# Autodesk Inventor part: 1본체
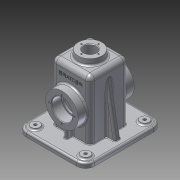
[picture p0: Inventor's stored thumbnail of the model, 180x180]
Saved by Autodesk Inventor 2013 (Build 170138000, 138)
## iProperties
Created: 2016-01
Part Number: 1본체
Material: 알루미늄 6061
Document SubType Name: Modeling
Designer: Administrator
Density: 2.71 g/cm^3
Mass: 805.142 g
Surface Area: 912.293 cm^2
Volume: 297.1 cm^3
Author: Administrator
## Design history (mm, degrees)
sketch "스케치1"
  geometry: L1 (-57.5, 65)-(57.5, 65); L2 (57.5, 65)-(57.5, -65); L3 (57.5, -65)-(-57.5, -65); L4 (-57.5, -65)-(-57.5, 65); L5 (-57.5, 65)-(57.5, -65); L6 (57.5, 65)-(-57.5, -65); 1 further point
  constraints: 12 end point, 2 midpoint, 2 parallel, 1 horizontal, 1 perpendicular
  dimensions: "d0" = 115 distance of L1.start L1.end; "d2" = 130 distance of L1.end L2.end
extrude "돌출1" new body sketch "스케치1" distance "d3" = 8; taper "d4" = 0 deg
fillet "모깎기1" dims "d5" = 15
sketch "스케치3"
  geometry: L1 (42.5, -60)-(-42.5, -60); L2 (-52.5, -50)-(-52.5, 50); L3 (-42.5, 60)-(42.5, 60); L4 (52.5, 50)-(52.5, -50); L5 (52.5, -60)-(-52.5, 60); L6 (-52.5, -60)-(52.5, 60); A1 r 10 centre (42.5, -50) between (42.5, -60) and (52.5, -50); A2 r 10 centre (42.5, 50) between (52.5, 50) and (42.5, 60); A3 r 10 centre (-42.5, 50) between (-42.5, 60) and (-52.5, 50); A4 r 10 centre (-42.5, -50) between (-52.5, -50) and (-42.5, -60); 1 further point
  constraints: 12 end point, 8 point on circle, 8 point on line, 8 tangent, 4 centre point, 3 equal radius, 2 midpoint, 2 parallel, 1 horizontal, 1 perpendicular
  dimensions: "d6" = 105 distance of L5.start L6.start; "d8" = 120 distance of L6.start L5.end; "d9" = 10 radius of A1
extrude "돌출2" join sketch "스케치3" distance "d10" = 2; taper "d11" = 0 deg
sketch "스케치7"
  geometry: L1 (-32.5, 32.5)-(32.5, 32.5); L2 (32.5, 32.5)-(32.5, -32.5); L3 (32.5, -32.5)-(-32.5, -32.5); L4 (-32.5, -32.5)-(-32.5, 32.5); L5 (-32.5, 32.5)-(32.5, -32.5); L6 (32.5, 32.5)-(-32.5, -32.5); 1 further point
  constraints: 12 end point, 2 midpoint, 2 parallel, 1 horizontal, 1 perpendicular
  dimensions: "d33" = 65 distance of L2.end L3.end; "d34" = 65 distance of L1.end L2.end
extrude "돌출4" join sketch "스케치7" distance "d35" = 100; taper "d36" = 0 deg
fillet "모깎기2" dims "d37" = 8
fillet "모깎기3" dims "d38" = 8
sketch "스케치8"
  geometry: C1 r 20 at (0, 0); 1 further point
  constraints: 1 centre point, 1 coincident
  dimensions: "d39" = 20 radius of C1
extrude "돌출5" join sketch "스케치8" distance "d40" = 10; taper "d41" = 0 deg
node "작업 평면1"
sketch "스케치10"
  geometry: L1 (-57.5, 0)-(-57.5, 8) reference; L2 (-57.5, 8)-(57.5, 8) reference; L3 (57.5, 8)-(57.5, 0) reference; L4 (52.5, 0)-(52.5, -2) reference; L5 (52.5, -2)-(-52.5, -2) reference; L6 (-52.5, -2)-(-52.5, 0) reference; L7 (-52.5, 0)-(-57.5, 0) reference; L8 (57.5, 0)-(52.5, 0) reference; C1 r 27.5 at (0, 53); 1 further point
  constraints: 1 centre point, 1 vertical alignment
  dimensions: "d44" = 55 diameter of C1; "d92" = 55 distance from line of L5 C1.centre
extrude "돌출6" join sketch "스케치10" stored distance "d45" = 10; taper "d46" = 0 deg
sketch "스케치11"
  geometry: C1 r 27.5 at (0, 0) reference; 1 further point
hole "구멍3" sketch "스케치11" at (0, 0) diameter "d47" = 30; stored, may be unused: countersink angle "d51" = 90 deg, drill point angle "d53" = 0 deg; dims "d48" = 6, "d49" = 35, "d50" = 17, "d52" = 20
sketch "스케치12"
  geometry: L1 (27.5, 27.5)-(-27.5, 27.5); L2 (-27.5, 27.5)-(-27.5, -27.5); L3 (-27.5, -27.5)-(27.5, -27.5); L4 (27.5, -27.5)-(27.5, 27.5); L5 (27.5, 27.5)-(-27.5, -27.5); L6 (-27.5, 27.5)-(27.5, -27.5); 1 further point
  constraints: 12 end point, 2 midpoint, 2 parallel, 1 horizontal, 1 perpendicular
  dimensions: "d54" = 55 distance of L2.end L3.end; "d56" = 55 distance of L3.end L1.start
extrude "돌출7" cut sketch "스케치12" distance "d57" = 105; taper "d58" = 0 deg
fillet "모깎기4" dims "d59" = 3
sketch "스케치13"
  geometry: C1 r 17.5 at (0, 0) reference; 2 further points
  constraints: 1 vertical alignment
  dimensions: "d60" = 21 distance of point (0, -21) C1.centre
hole "구멍4" sketch "스케치13" at (0, -21) diameter "d61" = 3.242; stored, may be unused: countersink angle "d65" = 90 deg, drill point angle "d67" = 118 deg; dims "d62" = 8, "d63" = 35, "d64" = 17, "d66" = 10
hole "구멍5" diameter "d73" = 21; stored, may be unused: countersink angle "d77" = 90 deg, drill point angle "d79" = 0 deg; dims "d71" = 10, "d72" = 10, "d74" = 8, "d75" = 35, "d76" = 17, "d78" = 10
feature "면 기울기1" dims angle "d80" = 5 deg
sketch "스케치14"
  geometry: C1 r 10.5 at (0, 0) reference; 1 further point
  constraints: 1 vertical alignment
  dimensions: "d81" = 14.5 distance of C1.centre point (0, -14.5)
hole "구멍6" sketch "스케치14" at (0, -14.5) diameter "d82" = 2.459; stored, may be unused: countersink angle "d86" = 90 deg, drill point angle "d88" = 118 deg; dims "d83" = 7, "d84" = 35, "d85" = 17, "d87" = 9
sketch "스케치15"
  geometry: C1 r 7.5 at (-42.5, -50); C2 r 7.5 at (42.5, -50); C3 r 7.5 at (-42.5, 50); C4 r 7.5 at (42.5, 50); A1 r 15 centre (42.5, 50) between (57.5, 50) and (42.5, 65) reference; A2 r 15 centre (-42.5, 50) between (-42.5, 65) and (-57.5, 50) reference; A3 r 15 centre (-42.5, -50) between (-57.5, -50) and (-42.5, -65) reference; A4 r 15 centre (42.5, -50) between (42.5, -65) and (57.5, -50) reference; 1 further point
  constraints: 4 centre point, 4 coincident
  dimensions: "d93" = 7.5 radius of C1; "d94" = 7.5 radius of C2; "d95" = 7.5 radius of C3; "d96" = 7.5 radius of C4
extrude "돌출8" join sketch "스케치15" distance "d97" = 3; taper "d98" = 0 deg
sketch "스케치16"
  geometry: L1 (-67, -77.5)-(-18, -77.5) reference; L2 (-15, -74.5)-(-15, -25.5) reference; L3 (-18, -22.5)-(-67, -22.5) reference; L4 (-70, -25.5)-(-70, -74.5) reference; L5 (-10, -25.5)-(-10, -74.5) reference; L6 (-18, -82.5)-(-67, -82.5) reference; L7 (-75, -74.5)-(-75, -25.5) reference; L8 (-67, -17.5)-(-18, -17.5) reference; C1 r 7.5 at (0, 0) reference; C2 r 7.5 at (-85, 0) reference; C3 r 7.5 at (-85, -100) reference; C4 r 7.5 at (0, -100) reference; C5 r 7.5 at (0, 0) reference; A1 r 3 centre (-67, -74.5) between (-70, -74.5) and (-67, -77.5) reference; A2 r 3 centre (-18, -74.5) between (-18, -77.5) and (-15, -74.5) reference; A3 r 3 centre (-18, -25.5) between (-15, -25.5) and (-18, -22.5) reference; A4 r 3 centre (-67, -25.5) between (-67, -22.5) and (-70, -25.5) reference; A5 r 8 centre (-18, -25.5) between (-10, -25.5) and (-18, -17.5) reference; A6 r 8 centre (-18, -74.5) between (-18, -82.5) and (-10, -74.5) reference; A7 r 8 centre (-67, -74.5) between (-75, -74.5) and (-67, -82.5) reference; A8 r 8 centre (-67, -25.5) between (-67, -17.5) and (-75, -25.5) reference; 1 further point
hole "구멍7" sketch "스케치16" at (-85, -100), (-85, 0), (0, 0), (0, -100) diameter "d99" = 5; stored, may be unused: countersink angle "d103" = 90 deg, drill point angle "d105" = 0 deg; dims "d100" = 5, "d101" = 35, "d102" = 17, "d104" = 9
sketch "스케치17"
  geometry: L1 (-52.5, -2)-(-52.5, 0) reference; L2 (-52.5, 0)-(-57.5, 0) reference; L3 (-57.5, 0)-(-57.5, 8) reference; L4 (-57.5, 8)-(-32.5, 8) reference; L5 (-32.5, 8)-(-32.5, 100) reference; L6 (-24.5, 108)-(-20.875, 108) reference; L7 (-20.875, 108)-(-20, 118) reference; L8 (-20, 118)-(-15.73, 118) reference; L9 (-15.73, 118)-(-15.73, 109) reference; L10 (-15.73, 109)-(-14.5, 108.261) reference; L11 (-14.5, 108.261)-(-13.271, 109) reference; L12 (-13.271, 109)-(-13.271, 118) reference; L13 (-13.271, 118)-(-10.5, 118) reference; L14 (-10.5, 118)-(-10.5, 103) reference; L15 (-10.5, 103)-(-27.5, 103) reference; L16 (-27.5, 103)-(-27.5, -2) reference; L17 (-27.5, -2)-(-52.5, -2) reference; L18 (52.5, 0)-(52.5, -2) reference; L19 (52.5, -2)-(27.5, -2) reference; L20 (27.5, -2)-(27.5, 103) reference; L21 (27.5, 103)-(10.5, 103) reference; L22 (10.5, 103)-(10.5, 118) reference; L23 (10.5, 118)-(13.271, 118) reference; L24 (13.271, 118)-(13.271, 109) reference; L25 (13.271, 109)-(14.5, 108.261) reference; L26 (14.5, 108.261)-(15.73, 109) reference; L27 (15.73, 109)-(15.73, 118) reference; L28 (15.73, 118)-(20, 118) reference; L29 (20, 118)-(20.875, 108) reference; L30 (20.875, 108)-(24.5, 108) reference; L31 (32.5, 100)-(32.5, 8) reference; L32 (32.5, 8)-(57.5, 8) reference; L33 (57.5, 8)-(57.5, 0) reference; L34 (57.5, 0)-(52.5, 0) reference; L35 (-57.5, 8)-(-42.5, 8) reference; L36 (-32.5, 100)-(-32.5, 8) reference; L37 (-32.5, 93.069)-(-47.5, 8); A1 r 8 centre (-24.5, 100) between (-24.5, 108) and (-32.5, 100) reference; A2 r 8 centre (24.5, 100) between (32.5, 100) and (24.5, 108) reference; 1 further point
  constraints: 2 end point, 2 point on line
  dimensions: "d107" = 10 distance from line of L37.end L3; "d108" = 10 deg angle of L3 L37
feature "리브1" sketch "스케치17" dims "d109" = 1, "d110" = 10, "d111" = 0, "d112" = 0, "d113" = 1, "d114" = 1
sketch "스케치18"
  geometry: L1 (0, -34.51)-(0, 0) reference; L2 (0, 0)-(49, 0) reference; L3 (49, -34.51)-(49, 0) reference; L4 (49, -92)-(49, -59.49) reference; L5 (49, -92)-(82, -92) reference; L6 (82, -92)-(82, -100) reference; L7 (82, -100)-(77, -100) reference; L8 (77, -100)-(77, -102) reference; L9 (77, -102)-(-28, -102) reference; L10 (-28, -102)-(-28, -100) reference; L11 (-28, -100)-(-33, -100) reference; L12 (-33, -100)-(-33, -92) reference; L13 (-33, -92)-(0, -92) reference; L14 (0, -92)-(49, -92) reference; L15 (0, -92)-(0, -59.49) reference; L16 (44.5, 18)-(4.5, 18) reference; L17 (-8, 0)-(-8, -92) reference; C1 r 17.5 at (24.5, -47) reference; A1 r 27.5 centre (24.5, -47) between (49, -34.51) and (0, -34.51) reference; A2 r 27.5 centre (24.5, -47) between (49, -59.49) and (49, -34.51) reference; A3 r 27.5 centre (24.5, -47) between (0, -59.49) and (49, -59.49) reference; A4 r 27.5 centre (24.5, -47) between (0, -34.51) and (0, -59.49) reference; 2 further points
  constraints: 1 other
  dimensions: "d115" = 27 distance from line of L16 point (24.5, -9); "d141" = 32.5 distance from line of point (24.5, -9) L17
feature "엠보싱1" sketch "스케치18" dims "d9" = 10, "d116" = 0.5, "d117" = 0
sketch "스케치19"
  geometry: L1 (24.5, -32.5)-(-24.5, -32.5) reference; L2 (0, -42.5)-(0, -42.5); L3 (3, -39.5)-(3, -32.5); L4 (3, -32.5)-(-3, -32.5); L5 (-3, -32.5)-(-3, -39.5); A1 r 3 centre (0, -39.5) between (-3, -39.5) and (0, -42.5); A2 r 3 centre (0, -39.5) between (0, -42.5) and (3, -39.5); 4 further points
  constraints: 8 end point, 4 point on circle, 4 point on line, 4 tangent, 2 centre point, 2 parallel, 1 collinear, 1 concentric, 1 horizontal, 1 midpoint, 1 perpendicular, 1 vertical alignment
  dimensions: "d120" = 6 distance of point (-3, -42.5) point (3, -42.5); "d130" = 3 radius of A1; "d133" = 7 distance from line of A2.centre L4
extrude "돌출9" join sketch "스케치19" stored distance "d121" = 15; taper "d122" = 0 deg
chamfer "모따기1" distance "d123" = 1; stored, may be unused: second distance "d124" = 2, angle "d125" = 45 deg
fillet "모깎기5" dims "d126" = 0.3
fillet "모깎기6" dims "d127" = 3
fillet "모깎기7" dims "d128" = 3
fillet "모깎기9" dims "d134" = 3
fillet "모깎기10" dims "d135" = 1
fillet "모깎기11" dims "d136" = 3
fillet "모깎기12" dims "d137" = 3
fillet "모깎기13" dims "d138" = 3
fillet "모깎기14" dims "d139" = 3
fillet "모깎기15" dims "d140" = 3
node "솔리드1"
mirror "대칭1"
pattern_circular "원형 패턴1" dims angle "d69" = 360 deg
mirror "대칭2"
pattern_circular "원형 패턴2" dims angle "d90" = 360 deg
mirror "대칭3"
mirror "대칭4"
node "절단 모서리 투영3"
node "절단 모서리 투영4"
node "절단 모서리 투영5"
node "절단 모서리 투영6"
other parameters: "d42" = 47.5
